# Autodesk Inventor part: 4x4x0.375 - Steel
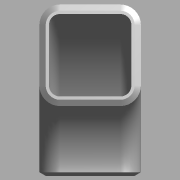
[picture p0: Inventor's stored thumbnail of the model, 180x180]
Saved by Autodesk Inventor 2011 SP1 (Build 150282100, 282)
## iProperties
Created: 2011-03
Part Number: 4x4x0.375 - Steel
Material: Default
Document SubType Name: Modeling
Designer: bamfomg
Density: 1 g/cm^3
Author: bamfomg
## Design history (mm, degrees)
derived "Square Tube Corners.ipt" dims "d2" = 50.8, "d3" = 50.8, "d6" = 9.525, "d7" = 9.525, "d8" = 9.525, "d12" = 90 deg, "d16" = 6.35, "d18" = 30 deg, "ID_Rad" = 11.1125, "OD_Rad" = 20.6375, "Side_One" = 101.6, "Side_Two" = 101.6, "Thickness" = 9.525, "Bend_IDRad" = 69.85, "Bevel_Angl" = 30 deg, "Bevel_Dist" = 6.35
body "Solid1"
feature "Solid1::Square Tube Corners.ipt" dims "d2" = 50.8, "d3" = 50.8, "d6" = 9.525, "d7" = 9.525, "d8" = 9.525, "d12" = 90 deg, "d16" = 6.35, "d18" = 30 deg, "ID_Rad" = 11.1125, "OD_Rad" = 20.6375, "Side_One" = 101.6, "Side_Two" = 101.6, "Thickness" = 9.525, "Bend_IDRad" = 69.85, "Bevel_Angl" = 30 deg, "Bevel_Dist" = 6.35, "ScaleForDerivedMember" = 10
tag "TaggingFeature1"
